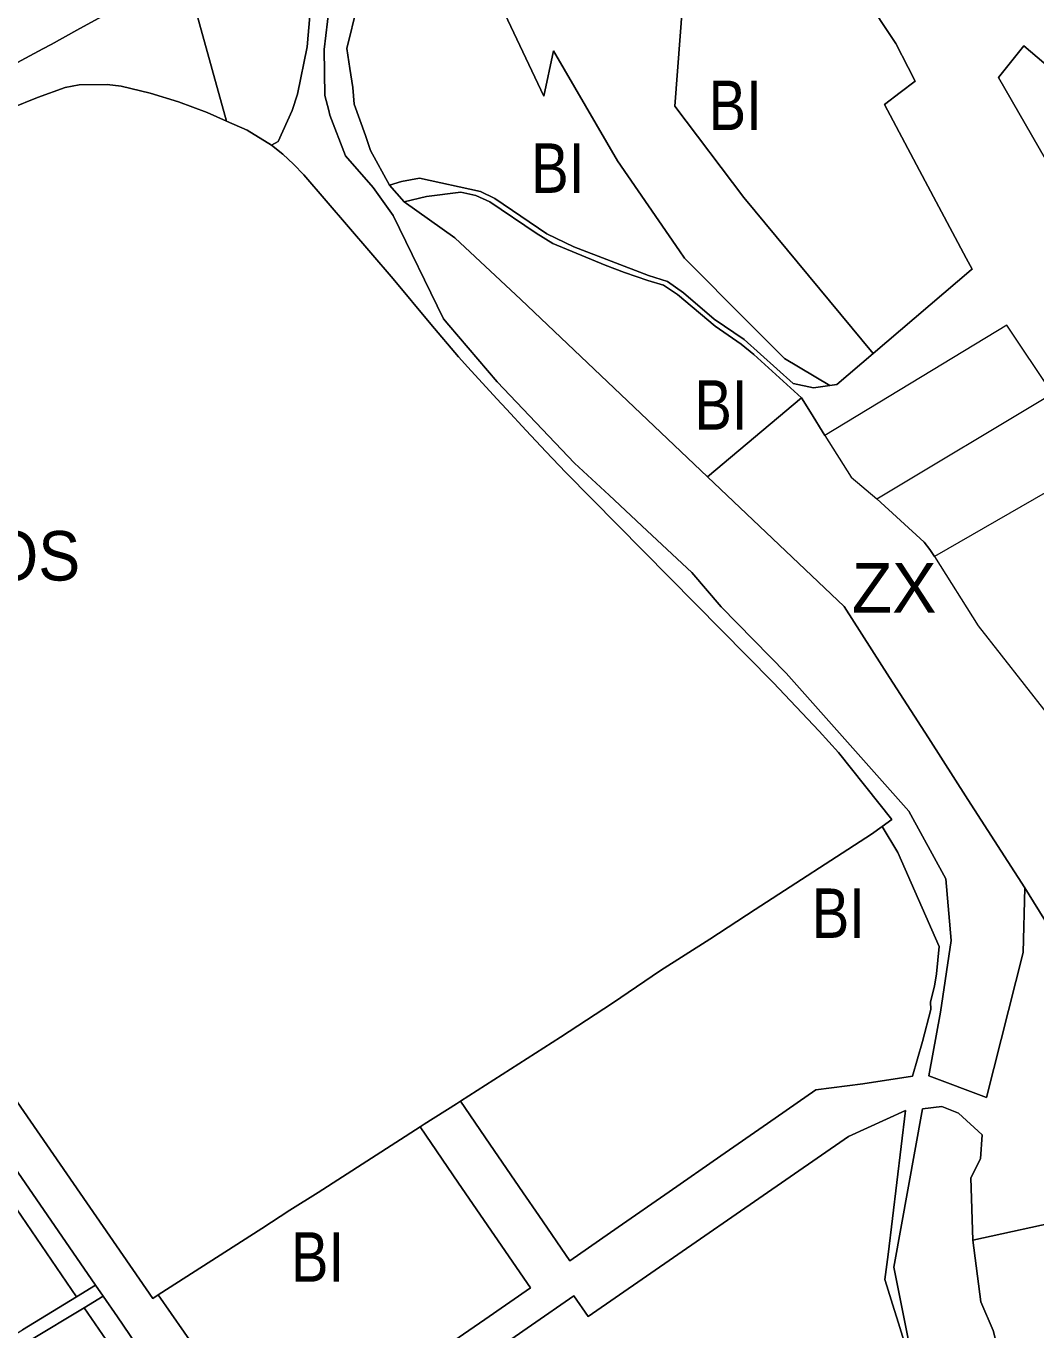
# Model space of a CAD drawing. Extents: x -650451 to -642268, y -1075216 to -1066610.
# Drawn here: x -646829.3 to -646584.6, y -1071698.5 to -1071382.4 of the extents above; entities that cross this region are included whole.
import ezdxf

# ---------------------------------------------------------------- set-up
doc = ezdxf.new("R2010")
doc.units = 0
doc.header["$LTSCALE"] = 4.8
for name, color, linetype, lineweight in [('15', 7, 'Continuous', 13), ('2', 7, 'Continuous', 13), ('40', 7, 'Continuous', 13), ('43', 7, 'Continuous', 13), ('45', 7, 'Continuous', 13), ('9', 7, 'Continuous', 13)]:
    doc.layers.add(name, color=color, linetype=linetype, lineweight=lineweight)
doc.layers.add('62', color=7, linetype='Continuous')

msp = doc.modelspace()

# ---------------------------------------------------------------- linework, layer by layer
at = {"layer": '15'}
for points in [[(-646769.88, -1071411.26), (-646768.23, -1071410.33), (-646764.81, -1071402.84), (-646763.57, -1071398.89), (-646761.2, -1071387.4), (-646760.13, -1071375.11), (-646760.98, -1071370.89), (-646766.63, -1071352.98), (-646768.74, -1071347.6), (-646770.68, -1071343.28), (-646772.9, -1071339.22), (-646774.56, -1071336.5), (-646790.16, -1071343.29), (-646794.05, -1071345.01), (-646800.98, -1071348.08), (-646814.45, -1071353.72), (-646810.58, -1071360.8), (-646802.44, -1071375.74), (-646790.81, -1071369.2), (-646780.78, -1071405.41)], [(-646845.01, -1071398.44), (-646825.27, -1071387.91), (-646823.26, -1071386.84), (-646817.06, -1071383.39), (-646808.3, -1071378.6), (-646812.52, -1071370.95), (-646817.35, -1071362.07), (-646819.16, -1071358.75), (-646820.07, -1071357.05), (-646823.84, -1071350.04), (-646829.39, -1071339.75)], [(-646624.067, -1071461.757), (-646600.28, -1071441.49), (-646600.04, -1071441.27), (-646601.48, -1071438.67), (-646611.42, -1071419.94), (-646621.29, -1071401.37), (-646617.5, -1071398.47), (-646613.9, -1071395.72), (-646615.57, -1071392.42), (-646618.52, -1071386.62), (-646641.59, -1071351.83)], [(-646755.89, -1071377.89), (-646757.12, -1071388.04), (-646756.9, -1071399.19), (-646756, -1071402.83), (-646755.72, -1071403.97), (-646751.89, -1071413.79), (-646745.22, -1071421.53), (-646740.34, -1071428.26), (-646728.15, -1071453.37), (-646726.89, -1071454.9), (-646715.17, -1071468.58), (-646696.39, -1071488.33), (-646688.01, -1071496.07), (-646678.85, -1071504.76), (-646667.97, -1071514.8), (-646660.9, -1071523.16), (-646645.15, -1071539.27), (-646615.44, -1071572.66), (-646606.4, -1071589.06), (-646605.14, -1071604.03), (-646607.7, -1071621.4), (-646610.58, -1071636.85), (-646596.55, -1071642.07), (-646587.71, -1071606.99), (-646587.29, -1071591.3)], [(-646483.58, -1071464.76), (-646504.28, -1071451.75), (-646509.94, -1071448.19), (-646510.63, -1071447.76), (-646512.01, -1071445.44), (-646529.94, -1071433.53), (-646535.05, -1071430.14), (-646545.77, -1071422.43), (-646572.96, -1071399.49), (-646587.53, -1071387.19), (-646593.69, -1071394.81), (-646561, -1071451.57), (-646550.03, -1071470.64), (-646536.06, -1071494.9)], [(-646780.78, -1071405.41), (-646785.47, -1071403.35), (-646792.42, -1071400.72), (-646799.24, -1071398.61), (-646806.27, -1071396.9), (-646809.67, -1071396.53), (-646816.49, -1071396.61), (-646819.88, -1071397.3), (-646826.6, -1071399.65), (-646832.97, -1071402.3)], [(-646812.491, -1071687.611), (-646845.66, -1071639.56), (-646864.39, -1071614.36), (-646884.4, -1071583.42), (-646965.35, -1071460.17), (-646976.09, -1071442.66), (-646981.06, -1071431.57), (-646984.18, -1071424.12), (-646989.58, -1071409.27)], [(-646621.87, -1071576.41), (-646619.55, -1071574.7), (-646632.44, -1071558.51), (-646637.11, -1071553.26), (-646648.3, -1071541.51), (-646698.49, -1071490.63), (-646703.35, -1071485.47), (-646708.15, -1071480.42), (-646712.92, -1071475.21), (-646715.24, -1071472.75), (-646722.24, -1071465.07), (-646724.51, -1071462.55), (-646731.25, -1071454.6), (-646740.38, -1071443.66), (-646762.06, -1071418.46), (-646764.49, -1071415.82), (-646767.14, -1071413.43), (-646769.88, -1071411.26)], [(-646741.26, -1071420.97), (-646738.38, -1071420.03), (-646734, -1071419.27), (-646719.23, -1071422.46), (-646715.7, -1071424.14), (-646703.15, -1071432.76), (-646696.59, -1071435.91), (-646678.5, -1071442.87), (-646673.89, -1071444.28), (-646670.05, -1071447.06), (-646662.55, -1071453.44), (-646655.29, -1071458.37), (-646643.4, -1071468.99), (-646638.52, -1071470.05), (-646634.56, -1071469.49)], [(-646641.4, -1071472.53), (-646652.96, -1071462.02), (-646656.05, -1071459.46), (-646662.34, -1071455.08), (-646671.43, -1071447.47), (-646674.83, -1071445.17), (-646678.69, -1071444.02), (-646684.31, -1071442.14), (-646689, -1071440.34), (-646701.68, -1071435.04), (-646705.75, -1071432.56), (-646716.94, -1071424.94), (-646720.33, -1071423.42), (-646724, -1071422.64), (-646732.28, -1071423.7), (-646737.72, -1071424.95), (-646741.26, -1071420.97)], [(-647010.73, -1071429.74), (-647008.5, -1071433.35), (-646997.05, -1071451.02), (-646983.8, -1071471.4), (-646944.58, -1071534.7), (-646916, -1071580.13), (-646903.67, -1071599.34), (-646872.61, -1071647.71), (-646842.09, -1071691.69), (-646835.177, -1071701.48), (-646830.204, -1071698.44), (-646817.081, -1071690.417), (-646812.491, -1071687.611), (-646810.635, -1071690.299), (-646815.26, -1071693.087), (-646828.461, -1071701.044)], [(-646580.58, -1071471.48), (-646591.65, -1071454.91), (-646635.79, -1071481.6)], [(-646634.56, -1071469.49), (-646632.85, -1071469.24), (-646624.067, -1071461.757)], [(-646635.79, -1071481.6), (-646639.27, -1071475.98), (-646641.4, -1071472.53)], [(-646885.33, -1071565.23), (-646798.65, -1071690.8), (-646797.35, -1071689.94)], [(-646724.04, -1071643.01), (-646716.97, -1071653.45), (-646708.84, -1071665.18), (-646705.05, -1071670.74), (-646697.57, -1071681.68), (-646685.84, -1071673.56), (-646673.45, -1071664.96), (-646660.99, -1071656.26), (-646649.67, -1071648.45), (-646637.96, -1071640.25), (-646626.51, -1071638.81), (-646614.53, -1071636.9), (-646612.06, -1071628.5), (-646610.03, -1071620.78), (-646610.17, -1071618.89), (-646609.2, -1071615.12), (-646608.72, -1071612.1), (-646608.01, -1071605.52), (-646618.09, -1071582.71), (-646621.87, -1071576.41)], [(-646587.29, -1071591.3), (-646568.26, -1071622.03), (-646561.68, -1071632.65)], [(-646733.84, -1071649.23), (-646732.85, -1071648.6), (-646725.01, -1071643.63), (-646724.04, -1071643.01)], [(-646599.91, -1071676.7), (-646600.39, -1071661.57), (-646598.02, -1071656.99), (-646597.62, -1071651.17), (-646603.36, -1071645.9), (-646607.42, -1071644.31), (-646612.06, -1071644.82), (-646619.02, -1071683.21), (-646615.23, -1071702.21)], [(-646616.6, -1071701.04), (-646617.9, -1071696.83), (-646619.34, -1071692.19), (-646620.7, -1071687.79), (-646621.18, -1071686.22), (-646620.42, -1071680.13), (-646616.17, -1071645.28), (-646630.03, -1071651.57), (-646693.14, -1071695.19), (-646696.62, -1071690.18), (-646706.85, -1071697.29), (-646762.17, -1071735.66)], [(-646797.35, -1071689.94), (-646787.88, -1071703.5), (-646780.45, -1071714.01), (-646769.84, -1071729.18), (-646767, -1071729.68), (-646756.4, -1071722.25), (-646750.1, -1071717.98), (-646743.89, -1071713.7), (-646737.37, -1071709.21), (-646730.81, -1071704.69), (-646718.12, -1071695.9), (-646707.07, -1071688.26), (-646724.53, -1071662.87), (-646733.84, -1071649.23)], [(-646537.83, -1071682.37), (-646546.14, -1071684.96), (-646546.29, -1071687.96), (-646550.69, -1071687.74), (-646550.94, -1071692.73), (-646561.25, -1071692.22), (-646576.23, -1071671.54), (-646599.91, -1071676.7)], [(-646715.81, -1071832.61), (-646710.82, -1071828.79), (-646743.9, -1071788.63), (-646761.95, -1071761.85), (-646773.79, -1071744.44), (-646807.19, -1071695.29), (-646810.635, -1071690.299), (-646812.491, -1071687.611)]]:
    msp.add_lwpolyline(points, dxfattribs=at)
at = {"layer": '2'}
msp.add_line((-646623.18, -1071496.99), (-646580.58, -1071471.48), dxfattribs=at)
for points in [[(-646624.067, -1071461.757), (-646655.359, -1071423.942), (-646672.1, -1071401.822), (-646669.64, -1071368.84), (-646681.99, -1071349.13), (-646713.984, -1071300.606), (-646719.621, -1071303.894), (-646734.791, -1071276.956), (-646730.681, -1071274.557), (-646769.34, -1071208.77), (-646772.35, -1071202.69), (-646790.22, -1071177.59), (-646792.06, -1071173.55), (-646796.684, -1071164.505), (-646791.84, -1071162.27), (-646796.67, -1071151.34), (-646795.19, -1071150.7), (-646798.88, -1071139.24), (-646811.73, -1071143.52), (-646825.46, -1071115.49)], [(-646796.032, -1071288.567), (-646777.059, -1071276.245), (-646766.102, -1071295.263), (-646751.311, -1071286.616), (-646713.98, -1071369.3), (-646717.1, -1071371.35), (-646716.25, -1071373.16), (-646703.84, -1071399.38), (-646701.52, -1071388.41), (-646686.04, -1071415.05), (-646671.02, -1071436.82), (-646669.77, -1071438.64), (-646654.25, -1071454.23), (-646645.57, -1071462.96), (-646634.56, -1071469.49)], [(-646741.26, -1071420.97), (-646745.87, -1071412.56), (-646747.08, -1071408.91), (-646749.84, -1071401.32), (-646750.13, -1071397.26), (-646750.89, -1071392.68), (-646751.62, -1071387.84), (-646749.13, -1071377.64), (-646750.24, -1071367.66), (-646753.65, -1071355.98), (-646765.11, -1071330.42), (-646786.11, -1071306.96), (-646796.032, -1071288.567)], [(-646829.39, -1071339.75), (-646823.84, -1071350.04), (-646820.07, -1071357.05), (-646819.16, -1071358.75), (-646817.35, -1071362.07), (-646812.52, -1071370.95), (-646808.3, -1071378.6), (-646817.06, -1071383.39), (-646823.26, -1071386.84), (-646825.27, -1071387.91), (-646845.01, -1071398.44)], [(-646641.59, -1071351.83), (-646618.52, -1071386.62), (-646615.57, -1071392.42), (-646613.9, -1071395.72), (-646617.5, -1071398.47), (-646621.29, -1071401.37), (-646611.42, -1071419.94), (-646601.48, -1071438.67), (-646600.04, -1071441.27), (-646600.28, -1071441.49), (-646624.067, -1071461.757)], [(-646536.06, -1071494.9), (-646550.03, -1071470.64), (-646561, -1071451.57), (-646593.69, -1071394.81), (-646587.53, -1071387.19), (-646572.96, -1071399.49), (-646545.77, -1071422.43), (-646535.05, -1071430.14), (-646529.94, -1071433.53), (-646512.01, -1071445.44), (-646510.63, -1071447.76), (-646509.94, -1071448.19), (-646504.28, -1071451.75), (-646483.58, -1071464.76)], [(-646634.56, -1071469.49), (-646638.52, -1071470.05), (-646643.4, -1071468.99), (-646655.29, -1071458.37), (-646662.55, -1071453.44), (-646670.05, -1071447.06), (-646673.89, -1071444.28), (-646678.5, -1071442.87), (-646696.59, -1071435.91), (-646703.15, -1071432.76), (-646715.7, -1071424.14), (-646719.23, -1071422.46), (-646734, -1071419.27), (-646738.38, -1071420.03), (-646741.26, -1071420.97)], [(-646737.72, -1071424.95), (-646732.28, -1071423.7), (-646724, -1071422.64), (-646720.33, -1071423.42), (-646716.94, -1071424.94), (-646705.75, -1071432.56), (-646701.68, -1071435.04), (-646689, -1071440.34), (-646684.31, -1071442.14), (-646678.69, -1071444.02), (-646674.83, -1071445.17), (-646671.43, -1071447.47), (-646662.34, -1071455.08), (-646656.05, -1071459.46), (-646652.96, -1071462.02), (-646641.4, -1071472.53), (-646664.2, -1071491.64)], [(-646664.2, -1071491.64), (-646709.47, -1071448.63), (-646725.39, -1071433.74), (-646737.72, -1071424.95)], [(-646580.58, -1071471.48), (-646571.06, -1071486.69), (-646570, -1071488.38), (-646609.21, -1071510.98)], [(-646609.21, -1071510.98), (-646610.28, -1071509.28), (-646611.7, -1071507.46), (-646623.18, -1071496.99)], [(-646724.04, -1071643.01), (-646699.78, -1071627.47), (-646687.23, -1071619.24), (-646675.59, -1071611.29), (-646663.65, -1071603.69), (-646652.66, -1071596.57), (-646624.45, -1071578.31), (-646621.87, -1071576.41)], [(-646621.87, -1071576.41), (-646618.09, -1071582.71), (-646608.01, -1071605.52), (-646608.72, -1071612.1), (-646609.2, -1071615.12), (-646610.17, -1071618.89), (-646610.03, -1071620.78), (-646612.06, -1071628.5), (-646614.53, -1071636.9), (-646626.51, -1071638.81), (-646637.96, -1071640.25), (-646649.67, -1071648.45), (-646660.99, -1071656.26), (-646673.45, -1071664.96), (-646685.84, -1071673.56), (-646697.57, -1071681.68), (-646705.05, -1071670.74), (-646708.84, -1071665.18), (-646716.97, -1071653.45), (-646724.04, -1071643.01)], [(-646797.35, -1071689.94), (-646772.18, -1071673.87), (-646765.39, -1071669.44), (-646758.58, -1071665.12), (-646733.84, -1071649.23)], [(-646733.84, -1071649.23), (-646724.53, -1071662.87), (-646707.07, -1071688.26), (-646718.12, -1071695.9), (-646730.81, -1071704.69), (-646737.37, -1071709.21), (-646743.89, -1071713.7), (-646750.1, -1071717.98), (-646756.4, -1071722.25), (-646767, -1071729.68), (-646769.84, -1071729.18), (-646780.45, -1071714.01), (-646787.88, -1071703.5), (-646797.35, -1071689.94)]]:
    msp.add_lwpolyline(points, dxfattribs=at)
at = {"layer": '40'}
msp.add_line((-646815.26, -1071693.087), (-646810.635, -1071690.299), dxfattribs=at)
for points in [[(-646780.78, -1071405.41), (-646790.81, -1071369.2), (-646802.44, -1071375.74), (-646810.58, -1071360.8), (-646814.45, -1071353.72), (-646800.98, -1071348.08), (-646794.05, -1071345.01), (-646790.16, -1071343.29), (-646774.56, -1071336.5), (-646772.9, -1071339.22), (-646770.68, -1071343.28), (-646768.74, -1071347.6), (-646766.63, -1071352.98), (-646760.98, -1071370.89), (-646760.13, -1071375.11), (-646761.2, -1071387.4), (-646763.57, -1071398.89), (-646764.81, -1071402.84), (-646768.23, -1071410.33), (-646769.88, -1071411.26)], [(-646769.88, -1071411.26), (-646775.74, -1071407.63), (-646780.78, -1071405.41)], [(-646989.58, -1071409.27), (-646984.18, -1071424.12), (-646981.06, -1071431.57), (-646976.09, -1071442.66), (-646965.35, -1071460.17), (-646884.4, -1071583.42), (-646864.39, -1071614.36), (-646845.66, -1071639.56), (-646812.491, -1071687.611), (-646817.081, -1071690.417)], [(-646817.081, -1071690.417), (-646888.65, -1071585.51), (-646955.98, -1071481.39), (-646986, -1071435.46), (-646989.58, -1071409.27)], [(-646810.635, -1071690.299), (-646807.19, -1071695.29), (-646773.79, -1071744.44), (-646761.95, -1071761.85), (-646743.9, -1071788.63), (-646710.82, -1071828.79), (-646715.81, -1071832.61)], [(-646715.81, -1071832.61), (-646806.41, -1071706.06), (-646815.26, -1071693.087)]]:
    msp.add_lwpolyline(points, dxfattribs=at)
at = {"layer": '43'}
msp.add_line((-646664.2, -1071491.64), (-646641.4, -1071472.53), dxfattribs=at)
for points in [[(-646825.46, -1071115.49), (-646811.73, -1071143.52), (-646798.88, -1071139.24), (-646795.19, -1071150.7), (-646796.67, -1071151.34), (-646791.84, -1071162.27), (-646796.684, -1071164.505), (-646792.06, -1071173.55), (-646790.22, -1071177.59), (-646772.35, -1071202.69), (-646769.34, -1071208.77), (-646730.681, -1071274.557), (-646734.791, -1071276.956), (-646719.621, -1071303.894), (-646713.984, -1071300.606), (-646681.99, -1071349.13), (-646669.64, -1071368.84), (-646672.1, -1071401.822), (-646655.359, -1071423.942), (-646624.067, -1071461.757)], [(-646634.56, -1071469.49), (-646645.57, -1071462.96), (-646654.25, -1071454.23), (-646669.77, -1071438.64), (-646671.02, -1071436.82), (-646686.04, -1071415.05), (-646701.52, -1071388.41), (-646703.84, -1071399.38), (-646716.25, -1071373.16), (-646717.1, -1071371.35), (-646713.98, -1071369.3), (-646751.311, -1071286.616), (-646766.102, -1071295.263), (-646777.059, -1071276.245), (-646796.032, -1071288.567)], [(-646624.067, -1071461.757), (-646632.85, -1071469.24), (-646634.56, -1071469.49)], [(-646641.4, -1071472.53), (-646639.27, -1071475.98), (-646635.79, -1071481.6)], [(-646635.79, -1071481.6), (-646629.37, -1071491.74), (-646623.18, -1071496.99)], [(-646587.29, -1071591.3), (-646591.4, -1071584.91), (-646601.08, -1071569.83), (-646610.64, -1071554.95), (-646620.09, -1071540.25), (-646631.11, -1071523.09), (-646664.2, -1071491.64)], [(-646623.18, -1071496.99), (-646611.7, -1071507.46), (-646610.28, -1071509.28), (-646609.21, -1071510.98)], [(-646609.21, -1071510.98), (-646598.63, -1071527.8), (-646565.17, -1071570.4), (-646555.78, -1071589.66), (-646545.89, -1071609.07), (-646537.28, -1071624.8), (-646561.68, -1071632.65)], [(-646561.68, -1071632.65), (-646568.26, -1071622.03), (-646587.29, -1071591.3)]]:
    msp.add_lwpolyline(points, dxfattribs=at)
at = {"layer": '45'}
msp.add_line((-646828.461, -1071701.044), (-646815.26, -1071693.087), dxfattribs=at)
for points in [[(-646796.032, -1071288.567), (-646786.11, -1071306.96), (-646765.11, -1071330.42), (-646753.65, -1071355.98), (-646750.24, -1071367.66), (-646749.13, -1071377.64), (-646751.62, -1071387.84), (-646750.89, -1071392.68), (-646750.13, -1071397.26), (-646749.84, -1071401.32), (-646747.08, -1071408.91), (-646745.87, -1071412.56), (-646741.26, -1071420.97), (-646737.72, -1071424.95)], [(-646587.29, -1071591.3), (-646587.71, -1071606.99), (-646596.55, -1071642.07), (-646610.58, -1071636.85), (-646607.7, -1071621.4), (-646605.14, -1071604.03), (-646606.4, -1071589.06), (-646615.44, -1071572.66), (-646645.15, -1071539.27), (-646660.9, -1071523.16), (-646667.97, -1071514.8), (-646678.85, -1071504.76), (-646688.01, -1071496.07), (-646696.39, -1071488.33), (-646715.17, -1071468.58), (-646726.89, -1071454.9), (-646728.15, -1071453.37), (-646740.34, -1071428.26), (-646745.22, -1071421.53), (-646751.89, -1071413.79), (-646755.72, -1071403.97), (-646756, -1071402.83), (-646756.9, -1071399.19), (-646757.12, -1071388.04), (-646755.89, -1071377.89)], [(-646989.58, -1071409.27), (-646986, -1071435.46), (-646955.98, -1071481.39), (-646888.65, -1071585.51), (-646817.081, -1071690.417), (-646830.204, -1071698.44)], [(-646737.72, -1071424.95), (-646725.39, -1071433.74), (-646709.47, -1071448.63), (-646664.2, -1071491.64)], [(-646664.2, -1071491.64), (-646631.11, -1071523.09), (-646620.09, -1071540.25), (-646610.64, -1071554.95), (-646601.08, -1071569.83), (-646591.4, -1071584.91), (-646587.29, -1071591.3)], [(-646615.23, -1071702.21), (-646619.02, -1071683.21), (-646612.06, -1071644.82), (-646607.42, -1071644.31), (-646603.36, -1071645.9), (-646597.62, -1071651.17), (-646598.02, -1071656.99), (-646600.39, -1071661.57), (-646599.91, -1071676.7)], [(-646599.91, -1071676.7), (-646597.99, -1071691.68), (-646594.93, -1071698.58), (-646591.55, -1071712), (-646590.67, -1071722.85), (-646588.13, -1071731.67), (-646589.23, -1071738.51), (-646591.81, -1071743.29), (-646597.62, -1071750.65), (-646603.02, -1071757.41), (-646611.33, -1071750.69), (-646605.08, -1071744.33), (-646603.88, -1071738.02), (-646604.63, -1071733.78), (-646607.94, -1071725.97), (-646615.23, -1071702.21)], [(-646815.26, -1071693.087), (-646806.41, -1071706.06), (-646715.81, -1071832.61)]]:
    msp.add_lwpolyline(points, dxfattribs=at)
at = {"layer": '9'}
for points in [[(-646832.97, -1071402.3), (-646826.6, -1071399.65), (-646819.88, -1071397.3), (-646816.49, -1071396.61), (-646809.67, -1071396.53), (-646806.27, -1071396.9), (-646799.24, -1071398.61), (-646792.42, -1071400.72), (-646785.47, -1071403.35), (-646780.78, -1071405.41)], [(-646780.78, -1071405.41), (-646775.74, -1071407.63), (-646769.88, -1071411.26)], [(-646769.88, -1071411.26), (-646767.14, -1071413.43), (-646764.49, -1071415.82), (-646762.06, -1071418.46), (-646740.38, -1071443.66), (-646731.25, -1071454.6), (-646724.51, -1071462.55), (-646722.24, -1071465.07), (-646715.24, -1071472.75), (-646712.92, -1071475.21), (-646708.15, -1071480.42), (-646703.35, -1071485.47), (-646698.49, -1071490.63), (-646648.3, -1071541.51), (-646637.11, -1071553.26), (-646632.44, -1071558.51), (-646619.55, -1071574.7), (-646621.87, -1071576.41)], [(-646797.35, -1071689.94), (-646798.65, -1071690.8), (-646885.33, -1071565.23)], [(-646621.87, -1071576.41), (-646624.45, -1071578.31), (-646652.66, -1071596.57), (-646663.65, -1071603.69), (-646675.59, -1071611.29), (-646687.23, -1071619.24), (-646699.78, -1071627.47), (-646724.04, -1071643.01)], [(-646724.04, -1071643.01), (-646725.01, -1071643.63), (-646732.85, -1071648.6), (-646733.84, -1071649.23)], [(-646762.17, -1071735.66), (-646706.85, -1071697.29), (-646696.62, -1071690.18), (-646693.14, -1071695.19), (-646630.03, -1071651.57), (-646616.17, -1071645.28), (-646620.42, -1071680.13), (-646621.18, -1071686.22), (-646620.7, -1071687.79), (-646619.34, -1071692.19), (-646617.9, -1071696.83), (-646616.6, -1071701.04)], [(-646733.84, -1071649.23), (-646758.58, -1071665.12), (-646765.39, -1071669.44), (-646772.18, -1071673.87), (-646797.35, -1071689.94)], [(-646599.91, -1071676.7), (-646576.23, -1071671.54), (-646561.25, -1071692.22), (-646550.94, -1071692.73), (-646550.69, -1071687.74), (-646546.29, -1071687.96), (-646546.14, -1071684.96), (-646537.83, -1071682.37)], [(-646615.23, -1071702.21), (-646607.94, -1071725.97), (-646604.63, -1071733.78), (-646603.88, -1071738.02), (-646605.08, -1071744.33), (-646611.33, -1071750.69), (-646603.02, -1071757.41), (-646597.62, -1071750.65), (-646591.81, -1071743.29), (-646589.23, -1071738.51), (-646588.13, -1071731.67), (-646590.67, -1071722.85), (-646591.55, -1071712), (-646594.93, -1071698.58), (-646597.99, -1071691.68), (-646599.91, -1071676.7)]]:
    msp.add_lwpolyline(points, dxfattribs=at)

# ---------------------------------------------------------------- texts
at = {"layer": '62'}
for s, width, p in [('BI', 0.85, (-646663.929, -1071407.583)), ('BI', 0.85, (-646706.923, -1071422.807)), ('BI', 0.85, (-646667.381, -1071480.223)), ('OS', 0.95, (-646838.249, -1071516.787)), ('BI', 0.85, (-646638.931, -1071603.432)), ('BI', 0.85, (-646765.145, -1071686.768))]:
    msp.add_text(s, height=12, dxfattribs=dict(at, width=width)).set_placement(p)
msp.add_text('ZX', height=12, dxfattribs=at).set_placement((-646629.23, -1071524.552))

doc.saveas('drawing.dxf')
